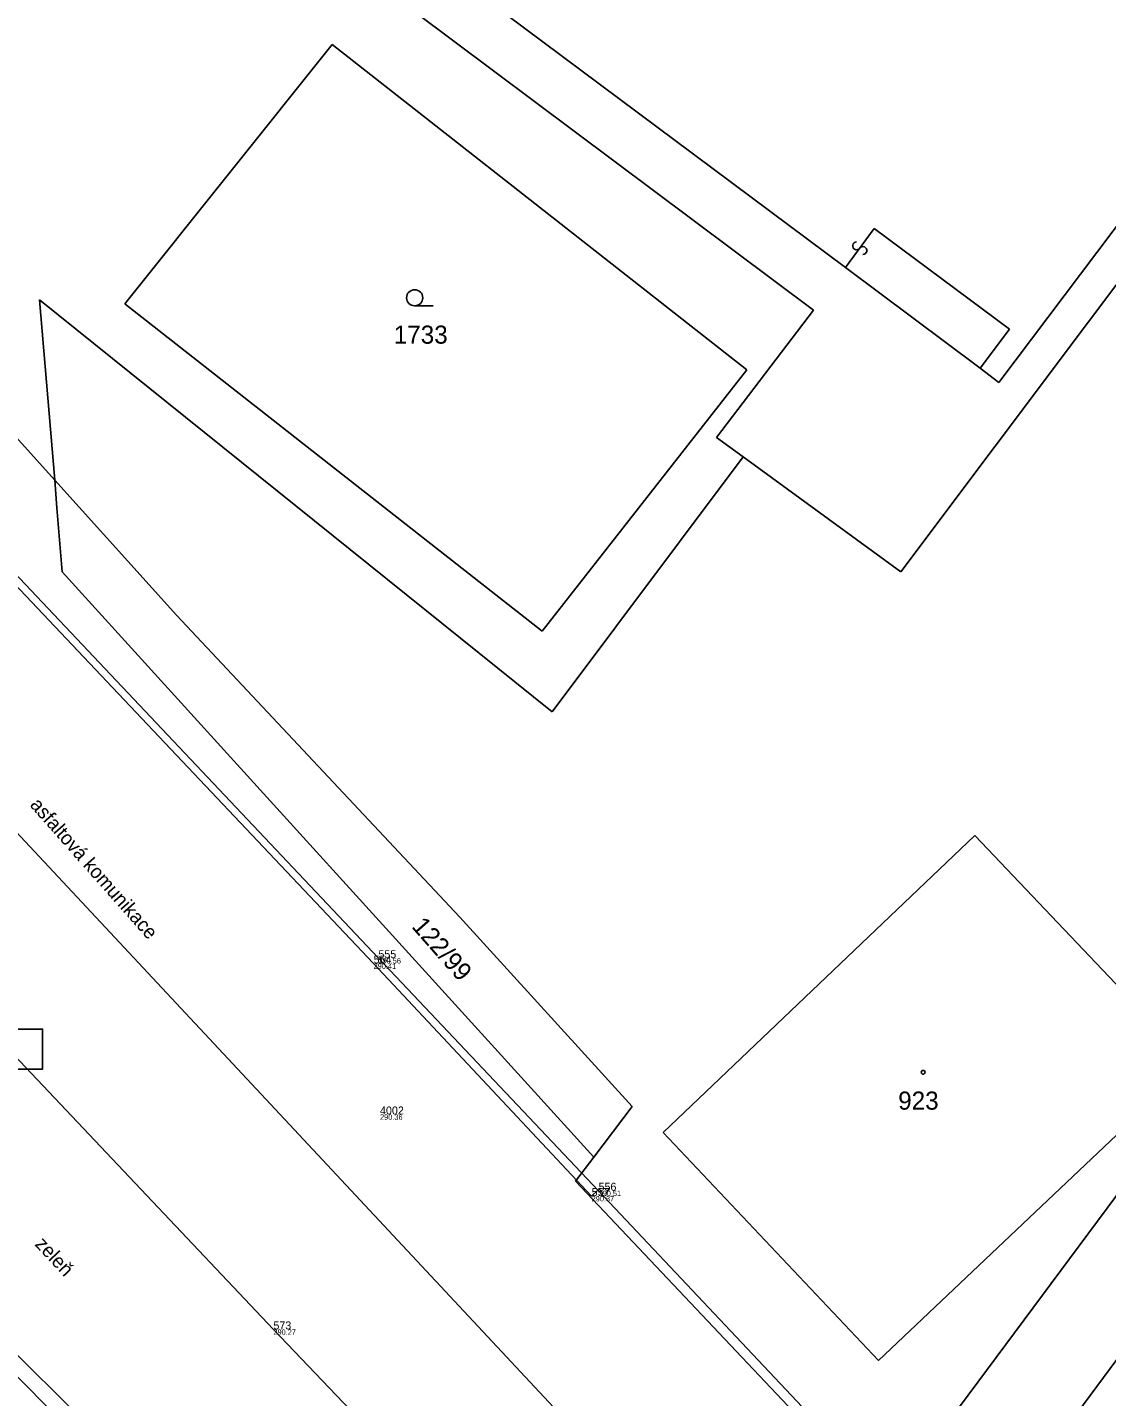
# Model space of a CAD drawing. Extents: x -805057 to -804930, y -994399 to -994240.
# Drawn here: x -804999.86 to -804979.61, y -994284.05 to -994258.38 of the extents above; entities that cross this region are included whole.
import ezdxf

# ---------------------------------------------------------------- set-up
doc = ezdxf.new("R2010")
doc.units = 0
for name, color, linetype in [('bod cislo', 7, 'Continuous'), ('bod pozice', 7, 'Continuous'), ('bod výška', 7, 'Continuous'), ('Katastralni mapa', 7, 'Continuous'), ('komunikace', 7, 'Continuous'), ('plot', 7, 'Continuous'), ('popis', 7, 'Continuous'), ('značka', 7, 'Continuous')]:
    doc.layers.add(name, color=color, linetype=linetype)

msp = doc.modelspace()

# ---------------------------------------------------------------- linework, layer by layer
at = {"layer": 'bod pozice'}
for p, q in [((-804993.36, -994275.93), (-804993.36, -994275.93)), ((-804993.27, -994275.83), (-804993.27, -994275.83)), ((-804993.24, -994278.76), (-804993.24, -994278.76)), ((-804989.27, -994280.29), (-804989.27, -994280.29)), ((-804989.14, -994280.19), (-804989.14, -994280.19)), ((-804995.24, -994282.79), (-804995.24, -994282.79))]:
    msp.add_line(p, q, dxfattribs=at)
at = {"layer": 'Katastralni mapa'}
for points in [[(-804981.44, -994286.08), (-804950.9, -994244.881)], [(-804974.66, -994256.85), (-804983.47, -994268.59)], [(-804975.52, -994256.93), (-804981.63, -994265.04)], [(-804984.51, -994262.88), (-804991.24, -994257.86)], [(-804985.11, -994263.68), (-804992.6, -994258.08)], [(-804998.03, -994263.56), (-804994.14, -994258.7)], [(-804994.14, -994258.7), (-804986.36, -994264.8)], [(-804963.36, -994258.68), (-804983.58, -994285.87)], [(-805003.78, -994261.95), (-804999.34, -994266.87)], [(-804984.51, -994262.88), (-804983.97, -994262.15)], [(-804983.97, -994262.15), (-804981.43, -994264.04)], [(-804984.51, -994262.88), (-804981.98, -994264.77)], [(-804990.01, -994271.21), (-804999.63, -994263.49)], [(-804999.34, -994266.87), (-804999.63, -994263.49)], [(-804990.2, -994269.7), (-804998.03, -994263.56)], [(-804992.591, -994263.6), (-804992.24, -994263.6)], [(-804986.93, -994266.07), (-804985.11, -994263.68)], [(-804981.43, -994264.04), (-804981.98, -994264.77)], [(-804986.36, -994264.8), (-804990.2, -994269.7)], [(-804981.98, -994264.77), (-804981.63, -994265.04)], [(-805017.39, -994266.11), (-804988.46, -994295.41)], [(-804986.43, -994266.43), (-804986.93, -994266.07)], [(-804986.43, -994266.43), (-804990.01, -994271.21)], [(-804983.47, -994268.59), (-804986.43, -994266.43)], [(-804999.3, -994267.39), (-804999.34, -994266.87)], [(-804999.34, -994266.87), (-804997.06, -994269.4)], [(-804999.2, -994268.59), (-804999.3, -994267.39)], [(-804989.23, -994279.56), (-804999.2, -994268.59)], [(-804997.06, -994269.4), (-804991.74, -994275.06)], [(-804987.93, -994279.1), (-804982.08, -994273.53)], [(-804982.08, -994273.53), (-804978.01, -994277.81)], [(-804991.74, -994275.06), (-804988.51, -994278.61)], [(-804978.01, -994277.81), (-804983.89, -994283.37)], [(-804988.51, -994278.61), (-804989.23, -994279.56)], [(-804983.89, -994283.37), (-804987.93, -994279.1)], [(-804989.23, -994279.56), (-804989.57, -994280.01)], [(-804989.57, -994280.01), (-804984.94, -994284.91), (-804983.58, -994285.87)]]:
    msp.add_lwpolyline(points, dxfattribs=at)
for centre, radius in [((-804992.59, -994263.449), 0.151), ((-804983.05, -994277.97), 0.0355)]:
    msp.add_circle(centre, radius, dxfattribs=at)
for centre, radius, start, end in [((-804984.299, -994262.476), 0.0735, 91.7598, 323.2884), ((-804984.181, -994262.564), 0.0738, 270.7764, 144.5244)]:
    msp.add_arc(centre, radius, start, end, dxfattribs=at)
at = {"layer": 'komunikace'}
for p, q in [((-805014.33, -994253.78), (-804993.36, -994275.93)), ((-804993.27, -994275.83), (-805014.23, -994253.66)), ((-804985.37, -994289.18), (-805005.75, -994267.39)), ((-804993.36, -994275.93), (-804989.27, -994280.29)), ((-804993.27, -994275.83), (-804989.14, -994280.19)), ((-804995.24, -994282.79), (-805000.77, -994276.95)), ((-804989.27, -994280.29), (-804989.151, -994280.179)), ((-804989.14, -994280.19), (-804985.01, -994284.57))]:
    msp.add_line(p, q, dxfattribs=at)
msp.add_lwpolyline([(-804990.63, -994287.72), (-804990.78, -994287.46), (-804995.24, -994282.79)], dxfattribs=at)
at = {"layer": 'plot'}
msp.add_line((-804992.39, -994290.82), (-805002.96, -994280.4), dxfattribs=at)
at = {"layer": 'značka'}
msp.add_lwpolyline([(-805001.07, -994277.91), (-804999.57, -994277.91), (-804999.57, -994277.16), (-805001.07, -994277.16)], close=True, dxfattribs=at)

# ---------------------------------------------------------------- texts
at = {"layer": 'bod cislo'}
for s, p in [('555    ', (-804993.27, -994275.83)), ('554    ', (-804993.36, -994275.93)), ('4002    ', (-804993.24, -994278.76)), ('556    ', (-804989.14, -994280.19)), ('557    ', (-804989.27, -994280.29)), ('573    ', (-804995.24, -994282.79))]:
    msp.add_text(s, height=0.15, dxfattribs=at).set_placement(p)
at = {"layer": 'bod výška'}
for s, p in [('290.41  ', (-804993.36, -994276.03)), ('290.56  ', (-804993.27, -994275.93)), ('290.36  ', (-804993.24, -994278.86)), ('290.37  ', (-804989.27, -994280.39)), ('290.51  ', (-804989.14, -994280.29)), ('290.27  ', (-804995.24, -994282.89))]:
    msp.add_text(s, height=0.1, dxfattribs=at).set_placement(p)
at = {"layer": 'Katastralni mapa'}
for s, p in [('1733', (-804992.982, -994264.31)), ('923', (-804983.519, -994278.67))]:
    msp.add_text(s, height=0.34, dxfattribs=at).set_placement(p)
msp.add_text('122/99', height=0.34, rotation=311.3823, dxfattribs=at).set_placement((-804992.662, -994275.244))
at = {"layer": 'popis'}
for s, height, rotation, p in [('asfaltová komunikace', 0.26289, 311.4538, (-804999.821, -994272.966)), ('zeleň', 0.2629, 313.0307, (-804999.729, -994281.203))]:
    msp.add_text(s, height=height, rotation=rotation, dxfattribs=at).set_placement(p)

doc.saveas('drawing.dxf')
